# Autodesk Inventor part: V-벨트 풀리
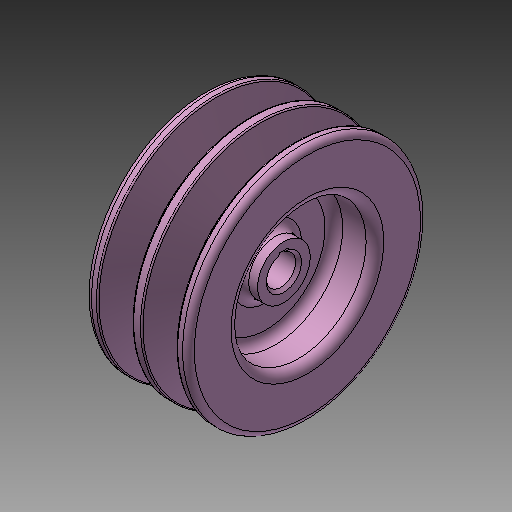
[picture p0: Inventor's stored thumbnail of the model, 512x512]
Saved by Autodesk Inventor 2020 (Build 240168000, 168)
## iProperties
Created: 2024-01
Part Number: V-벨트 풀리
Material: 강철, 주조
Document SubType Name: Modeling
Designer: mdu-01
Density: 1 g/cm^3
Appearance: 기본값(1)
Author: mdu-01
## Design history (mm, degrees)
sketch "스케치1"
  geometry: L1 (-9.5, 0)-(9.5, 0); L2 (-9.5, 6)-(-9.5, 9); L3 (-9.5, 9)-(-6.5, 9); L4 (-3.5, 12)-(-3.5, 20); L5 (-6.5, 23)-(-14.5, 23); L6 (-17.5, 26)-(-17.5, 38.5); L7 (0, 0)-(0, 40.5); L8 (9.5, 9)-(6.5, 9); L9 (9.5, 6)-(9.5, 9); L10 (3.5, 12)-(3.5, 20); L11 (6.5, 23)-(14.5, 23); L12 (17.5, 26)-(17.5, 38.5); L13 (-8.5, 5)-(8.5, 5); L14 (-9.5, 6)-(-8.5, 5); L15 (9.5, 6)-(8.5, 5); L16 (-7.5, 40.5)-(-7.5, 28); L17 (-13.368, 40.146)-(-9.87, 28.708); L18 (-1.632, 40.146)-(-5.13, 28.708); L19 (-8.914, 28)-(-6.086, 28); L20 (-15.5, 40.5)-(-13.846, 40.5); L21 (8.914, 28)-(6.086, 28); L22 (1.632, 40.146)-(5.13, 28.708); L23 (13.368, 40.146)-(9.87, 28.708); L24 (-1.154, 40.5)-(1.154, 40.5); L25 (13.846, 40.5)-(15.5, 40.5); A1 r 3 centre (-6.5, 12) between (-6.5, 9) and (-3.5, 12); A2 r 3 centre (-6.5, 20) between (-3.5, 20) and (-6.5, 23); A3 r 3 centre (-14.5, 26) between (-17.5, 26) and (-14.5, 23); A4 r 2 centre (-15.5, 38.5) between (-15.5, 40.5) and (-17.5, 38.5); A5 r 3 centre (6.5, 12) between (3.5, 12) and (6.5, 9); A6 r 3 centre (6.5, 20) between (6.5, 23) and (3.5, 20); A7 r 2 centre (15.5, 38.5) between (17.5, 38.5) and (15.5, 40.5); A8 r 3 centre (14.5, 26) between (14.5, 23) and (17.5, 26); A9 r 1 centre (-8.914, 29) between (-9.87, 28.708) and (-8.914, 28); A10 r 1 centre (-6.086, 29) between (-6.086, 28) and (-5.13, 28.708); A11 r 0.5 centre (-13.846, 40) between (-13.368, 40.146) and (-13.846, 40.5); A12 r 0.5 centre (-1.154, 40) between (-1.154, 40.5) and (-1.632, 40.146); A13 r 0.5 centre (1.154, 40) between (1.632, 40.146) and (1.154, 40.5); A14 r 1 centre (6.086, 29) between (5.13, 28.708) and (6.086, 28); A15 r 1 centre (8.914, 29) between (8.914, 28) and (9.87, 28.708); A16 r 0.5 centre (13.846, 40) between (13.846, 40.5) and (13.368, 40.146); 12 further points
  constraints: 50 end point, 32 point on circle, 32 symmetric about line, 19 point on line, 19 tangent, 16 centre point, 8 perpendicular, 6 parallel, 4 equal radius, 3 midpoint, 1 coincident, 1 horizontal, 8 other
  dimensions: "d0" = 19 distance of L1.start L1.end; "d1" = 3 radius of A1; "d2" = 2 radius of A4; "d3" = 18 diameter of L3 L1; "d4" = 10 diameter of L13 L1; "d5" = 1 distance of L2.start point (-9.5, 5); "d6" = 1 distance of L13.start point (-9.5, 5) (= d5); "d7" = 1 distance of L9.start point (9.5, 5) (= d5); "d8" = 1 distance of L13.end point (9.5, 5) (= d7); "d9" = 7 distance between parallel lines of L10 L4; "d10" = 46 diameter of L5 L1; "d11" = 35 distance between parallel lines of L12 L6; "d13" = 72 diameter of point (-12.1, 36) L1; "d14" = 34 deg angle of L18 L17; "d15" = 9.2 diameter of point (-12.1, 36) L16; "d16" = 15 diameter of L16 L7; "d17" = 8 distance from line of L19 point (-12.1, 36); "d18" = 4.5 distance from line of L20 point (-12.1, 36); "d19" = 1 radius of A9; "d20" = 0.5 radius of A11
revolve "회전1" sketch "스케치1" stored, may be unused: angle "d21" = 90 deg
sketch "스케치2"
  geometry: L1 (-1.5, 4.77)-(1.5, 4.77); L2 (1.5, 4.77)-(1.5, 6.4); L3 (1.5, 6.4)-(-1.5, 6.4); L4 (-1.5, 6.4)-(-1.5, 4.77); A1 r 5 centre (0, 0) between (-1.5, 4.77) and (1.5, 4.77) reference; 2 further points
  constraints: 8 end point, 3 point on circle, 2 parallel, 1 horizontal, 1 perpendicular, 1 vertical alignment
  dimensions: "d22" = 3 distance between parallel lines of L2 L4; "d24" = 11.4 distance from line of point (0, -5) L3
extrude "돌출1" cut sketch "스케치2" extent not by distance; stored distance "d25" = 10; taper "d26" = 0 deg
node "솔리드1"
other parameters: "d12" = 81
